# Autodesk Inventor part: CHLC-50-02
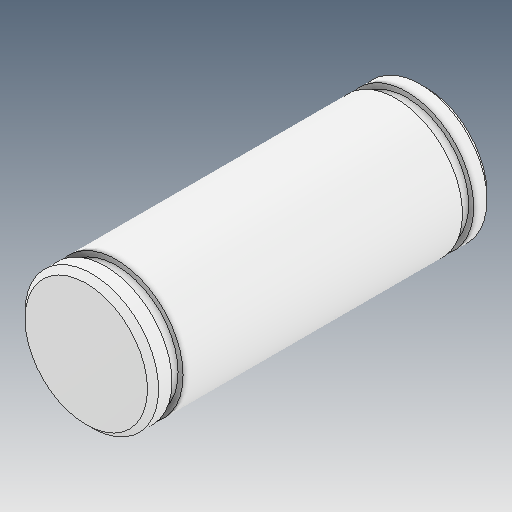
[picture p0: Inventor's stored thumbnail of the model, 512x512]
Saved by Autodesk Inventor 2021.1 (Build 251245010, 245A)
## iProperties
Created: 2021-05
Part Number: CHLC-50-02
Material: Ogólny
Document SubType Name: Modeling
Designer: user
Density: 1 g/cm^3
Appearance: Domyślna
Author: user
Revision Number: ÈÎºÎ
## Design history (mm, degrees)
feature "ÊäÈë1"
node "Bryła1"
